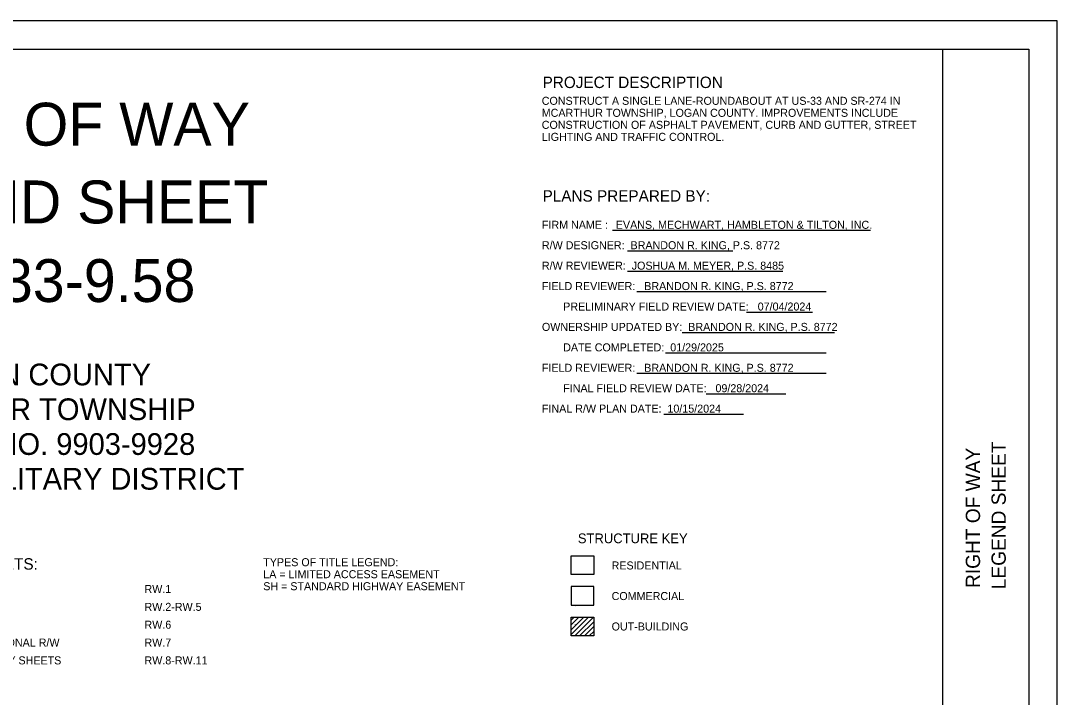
# Model space of a CAD drawing. Extents: x 0 to 34, y -5.4 to 22.
# Drawn here: x 15.87 to 34, y 10.17 to 22 of the extents above; entities that cross this region are included whole.
import ezdxf

# ---------------------------------------------------------------- set-up
doc = ezdxf.new("R2010")
doc.units = 0
for name, color, linetype in [('SC_Shading1', 7, 'Continuous'), ('SH_Border', 7, 'Continuous'), ('SH_Cut_Line', 7, 'Continuous'), ('SH_Data', 7, 'Continuous'), ('SH_Text', 7, 'Continuous')]:
    doc.layers.add(name, color=color, linetype=linetype)

msp = doc.modelspace()

# ---------------------------------------------------------------- linework, layer by layer
at = {"layer": 'SC_Shading1'}
msp.add_lwpolyline([(25.498, 11.781), (25.896, 11.781), (25.896, 12.107), (25.498, 12.107)], close=True, dxfattribs=at)
at = {"layer": 'SH_Border'}
msp.add_line((32, 0.5), (32, 21.5), dxfattribs=at)
msp.add_lwpolyline([(1.5, 21.5), (33.5, 21.5), (33.5, 0.5), (1.5, 0.5)], close=True, dxfattribs=at)
at = {"layer": 'SH_Cut_Line'}
msp.add_lwpolyline([(0, 0), (34, 0), (34, 22), (0, 22)], close=True, dxfattribs=at)
at = {"layer": 'SH_Text'}
for p, q in [((26.22, 18.336), (30.734, 18.336)), ((26.484, 17.979), (28.327, 17.979)), ((26.484, 17.622), (29.2, 17.622)), ((26.648, 17.265), (29.957, 17.265)), ((28.567, 16.907), (29.722, 16.907)), ((27.439, 16.55), (30.106, 16.55)), ((27.149, 16.193), (29.957, 16.193)), ((26.648, 15.836), (29.957, 15.836)), ((27.86, 15.479), (29.251, 15.479)), ((27.122, 15.122), (28.512, 15.122)), ((25.568, 11.763), (25.569, 11.764)), ((25.498, 11.52), (25.55, 11.571)), ((25.498, 11.435), (25.635, 11.571)), ((25.498, 11.351), (25.719, 11.571)), ((25.498, 11.266), (25.804, 11.571)), ((25.563, 11.245), (25.889, 11.571)), ((25.568, 11.443), (25.572, 11.438)), ((25.648, 11.245), (25.896, 11.493)), ((25.732, 11.245), (25.896, 11.409)), ((25.817, 11.245), (25.896, 11.324))]:
    msp.add_line(p, q, dxfattribs=at)
for points in [[(25.498, 12.642), (25.896, 12.642), (25.896, 12.316), (25.498, 12.316)], [(25.498, 11.571), (25.896, 11.571), (25.896, 11.245), (25.498, 11.245)]]:
    msp.add_lwpolyline(points, close=True, dxfattribs=at)

# ---------------------------------------------------------------- texts
at = {"layer": 'SH_Data'}
for s, height, p in [('RIGHT OF WAY', 0.75, (12.527, 19.816)), ('LEGEND SHEET', 0.75, (12.458, 18.457)), ('LOG-33-9.58', 0.75, (13.075, 17.082)), ('LOGAN COUNTY', 0.38, (14.087, 15.625)), ('McARTHUR TOWNSHIP', 0.38, (13.26, 15.017)), ('SURVEY NO. 9903-9928', 0.38, (13.22, 14.409)), ('VIRGINIA MILITARY DISTRICT', 0.38, (12.587, 13.801)), ('INDEX OF SHEETS:', 0.2, (13.692, 12.403)), ('RW.1', 0.14, (18.038, 11.994)), ('RW.2-RW.5', 0.14, (18.038, 11.682)), ('RW.6', 0.14, (18.038, 11.37)), ('SUMMARY OF ADDITIONAL R/W', 0.14, (13.692, 11.058)), ('RW.7', 0.14, (18.038, 11.058)), ('TOPO AND BOUNDARY SHEETS', 0.14, (13.692, 10.746)), ('RW.8-RW.11', 0.14, (18.038, 10.746))]:
    msp.add_text(s, height=height, dxfattribs=at).set_placement(p)
for s, p in [('RIGHT OF WAY', (32.65, 12.082)), ('LEGEND SHEET', (33.1, 12.06))]:
    msp.add_text(s, height=0.25, rotation=90, dxfattribs=at).set_placement(p)
at = {"layer": 'SH_Text'}
for s, height, p in [('PROJECT DESCRIPTION', 0.2, (25, 20.823)), ('CONSTRUCT A SINGLE LANE-ROUNDABOUT AT US-33 AND SR-274 IN ', 0.14, (24.985, 20.53)), ('MCARTHUR TOWNSHIP, LOGAN COUNTY. IMPROVEMENTS INCLUDE ', 0.14, (24.985, 20.32)), ('CONSTRUCTION OF ASPHALT PAVEMENT, CURB AND GUTTER, STREET ', 0.14, (24.985, 20.11)), ('LIGHTING AND TRAFFIC CONTROL.', 0.14, (24.985, 19.9)), ('PLANS PREPARED BY:', 0.2, (25, 18.837)), ('FIRM NAME : ', 0.14, (24.988, 18.362)), (' EVANS, MECHWART, HAMBLETON & TILTON, INC.', 0.14, (26.228, 18.362)), ('R/W DESIGNER:  BRANDON R. KING, P.S. 8772', 0.14, (24.988, 18.005)), ('R/W REVIEWER:  JOSHUA M. MEYER, P.S. 8485', 0.14, (24.988, 17.648)), ('FIELD REVIEWER:   BRANDON R. KING, P.S. 8772', 0.14, (24.988, 17.291)), ('PRELIMINARY FIELD REVIEW DATE:   07/04/2024', 0.14, (25.36, 16.933)), ('OWNERSHIP UPDATED BY:  BRANDON R. KING, P.S. 8772', 0.14, (24.988, 16.577)), ('DATE COMPLETED:  01/29/2025', 0.14, (25.36, 16.219)), ('FIELD REVIEWER:   BRANDON R. KING, P.S. 8772', 0.14, (24.988, 15.862)), ('FINAL FIELD REVIEW DATE:   09/28/2024', 0.14, (25.36, 15.505)), ('FINAL R/W PLAN DATE:  10/15/2024', 0.14, (24.988, 15.148)), ('STRUCTURE KEY', 0.17, (25.616, 12.865)), ('TYPES OF TITLE LEGEND:', 0.14, (20.115, 12.463)), ('RESIDENTIAL', 0.14, (26.207, 12.406)), ('LA = LIMITED ACCESS EASEMENT', 0.14, (20.115, 12.253)), ('SH = STANDARD HIGHWAY EASEMENT', 0.14, (20.115, 12.043)), ('COMMERCIAL', 0.14, (26.207, 11.871)), ('OUT-BUILDING', 0.14, (26.207, 11.339))]:
    msp.add_text(s, height=height, dxfattribs=at).set_placement(p)

doc.saveas('drawing.dxf')
